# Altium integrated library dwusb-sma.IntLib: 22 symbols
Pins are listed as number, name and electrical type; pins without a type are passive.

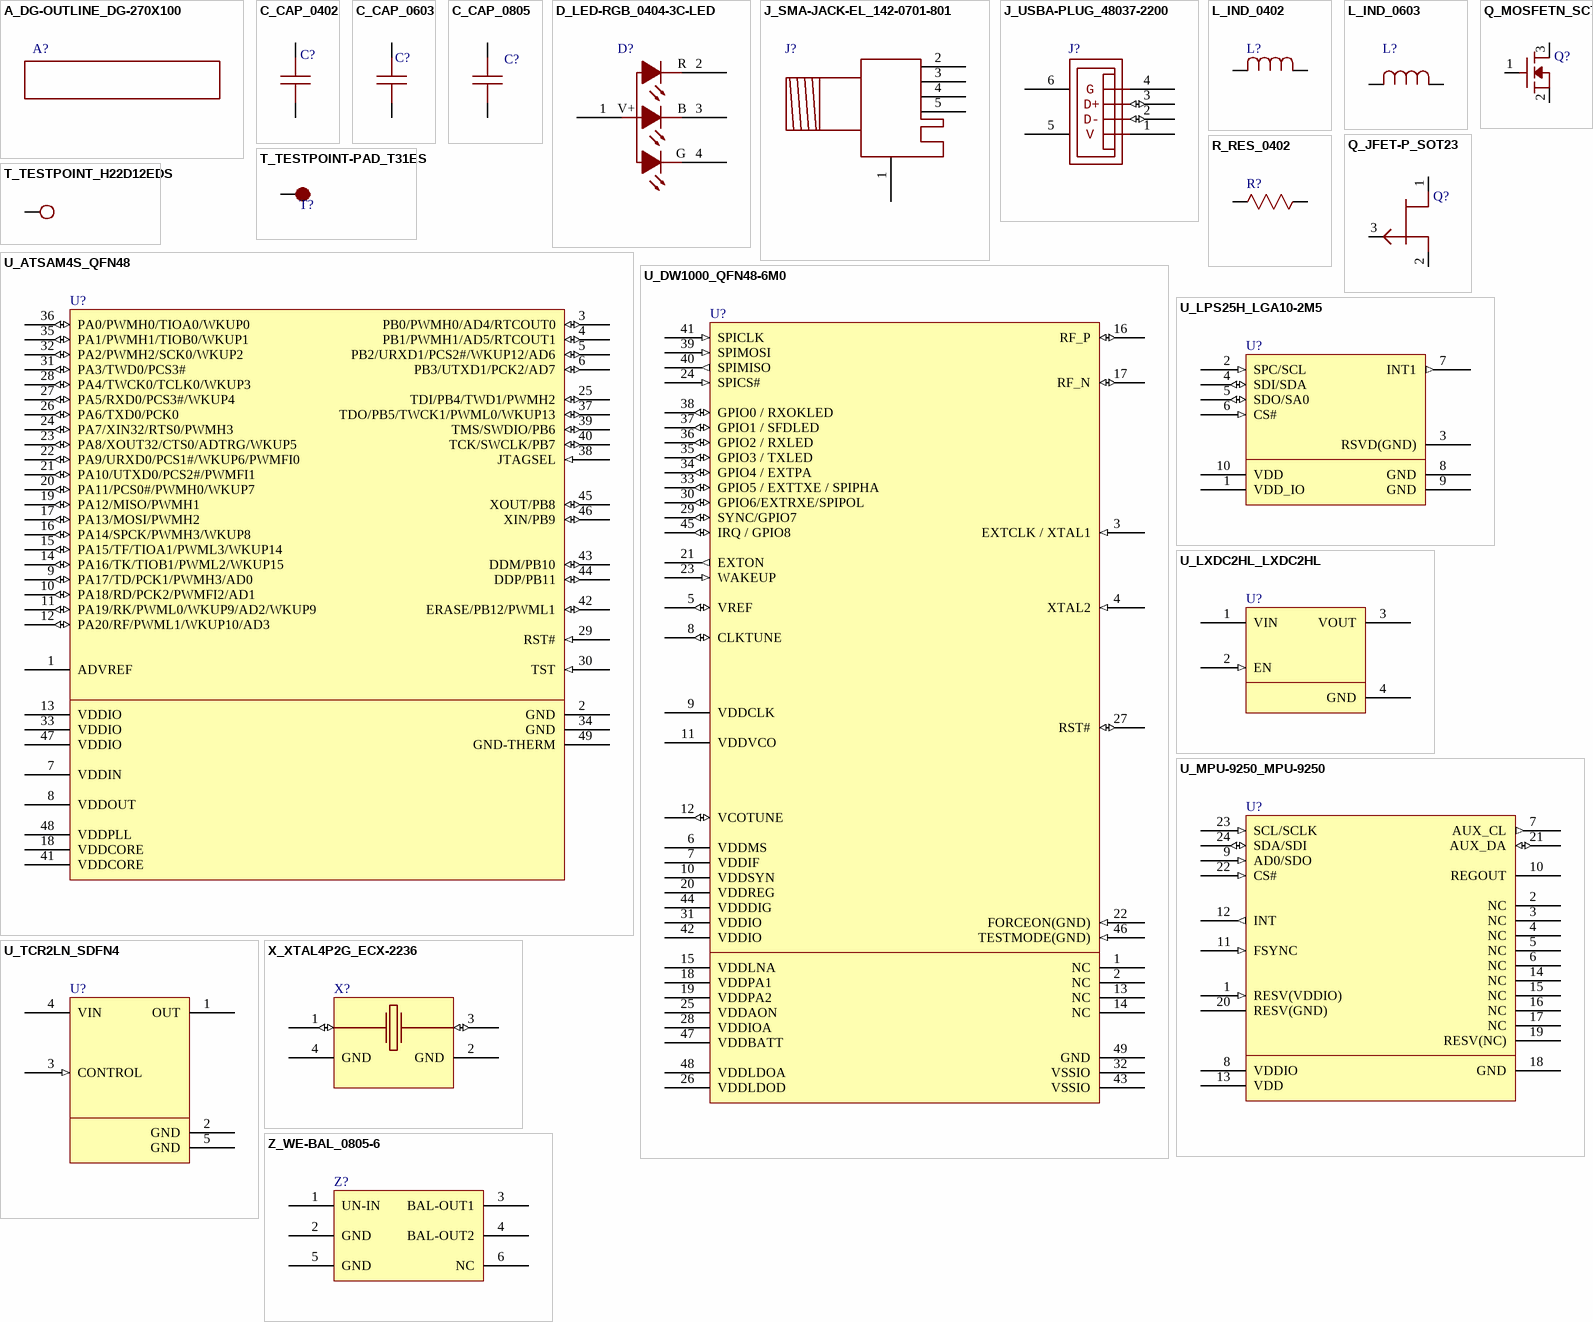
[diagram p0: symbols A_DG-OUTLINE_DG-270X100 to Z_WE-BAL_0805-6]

## A_DG-OUTLINE_DG-270X100
designator A?, comment A_DG-OUTLINE-DG-270X100  (value not drawn)
footprint DG-270X100

## C_CAP_0402
designator C?  (value not drawn)
footprint 0402
pins: 1, 2

## C_CAP_0603
designator C?  (value not drawn)
footprint 0603
pins: 1, 2

## C_CAP_0805
designator C?  (value not drawn)
footprint 0805
footprint 0805-S26
pins: 1, 2

## D_LED-RGB_0404-3C-LED
designator D?, comment LED RGB SQUARE CLEAR SMD  (value not drawn)
footprint 0404-3C-LED
pins: 1 V+, 2 R, 3 B, 4 G

## J_SMA-JACK-EL_142-0701-801
designator J?, comment J01340  (value not drawn)
footprint 142-0701-801
pins: 1, 2, 3, 4, 5

## J_USBA-PLUG_48037-2200
designator J?  (value not drawn)
footprint 48037-2200
pins: 1 +5V (power), 2 -DATA (io), 3 +DATA (io), 4 GND (power), 5 SHIELD (power), 6 SHIELD (power)

## L_IND_0402
designator L?  (value not drawn)
footprint 0402
pins: 1, 2

## L_IND_0603
designator L?  (value not drawn)
footprint 0603
pins: 1, 2

## Q_JFET-P_SOT23
designator Q?  (value not drawn)
footprint SOT23
pins: 1 D, 2 S, 3 G

## Q_MOSFETN_SC70
designator Q?, comment Q00171  (value not drawn)
footprint SC70
pins: 1 G, 2 S, 3 D

## R_RES_0402
designator R?  (value not drawn)
footprint 0402
pins: 1, 2

## T_TESTPOINT-PAD_T31ES
designator T?  (value not drawn)
footprint T31ES
pins: 1

## T_TESTPOINT_H22D12EDS
designator T?  (value not drawn)
footprint H22D12EDS
pins: 1

## U_ATSAM4S_QFN48
designator U?, comment U00965  (value not drawn)
footprint QFN48
pins: 1 ADVREF (power), 2 GND (power), 3 PB0/PWMH0/AD4/RTCOUT0 (io), 4 PB1/PWMH1/AD5/RTCOUT1 (io), 5 PB2/URXD1/PCS2#/WKUP12/AD6 (io), 6 PB3/UTXD1/PCK2/AD7 (io), 7 VDDIN (power), 8 VDDOUT (power), 9 PA17/TD/PCK1/PWMH3/AD0 (io), 10 PA18/RD/PCK2/PWMFI2/AD1 (io), 11 PA19/RK/PWML0/WKUP9/AD2/WKUP9 (io), 12 PA20/RF/PWML1/WKUP10/AD3 (io), 13 VDDIO (power), 14 PA16/TK/TIOB1/PWML2/WKUP15 (io), 15 PA15/TF/TIOA1/PWML3/WKUP14 (io), 16 PA14/SPCK/PWMH3/WKUP8 (io), 17 PA13/MOSI/PWMH2 (io), 18 VDDCORE (power), 19 PA12/MISO/PWMH1 (io), 20 PA11/PCS0#/PWMH0/WKUP7 (io), 21 PA10/UTXD0/PCS2#/PWMFI1 (io), 22 PA9/URXD0/PCS1#/WKUP6/PWMFI0 (io), 23 PA8/XOUT32/CTS0/ADTRG/WKUP5 (io), 24 PA7/XIN32/RTS0/PWMH3 (io), 25 TDI/PB4/TWD1/PWMH2 (io), 26 PA6/TXD0/PCK0 (io), 27 PA5/RXD0/PCS3#/WKUP4 (io), 28 PA4/TWCK0/TCLK0/WKUP3 (io), 29 RST# (in), 30 TST (in), 31 PA3/TWD0/PCS3# (io), 32 PA2/PWMH2/SCK0/WKUP2 (io), 33 VDDIO (power), 34 GND (power), 35 PA1/PWMH1/TIOB0/WKUP1 (io), 36 PA0/PWMH0/TIOA0/WKUP0 (io), 37 TDO/PB5/TWCK1/PWML0/WKUP13 (io), 38 JTAGSEL (in), 39 TMS/SWDIO/PB6 (io), 40 TCK/SWCLK/PB7 (io), 41 VDDCORE (power), 42 ERASE/PB12/PWML1 (io), 43 DDM/PB10 (io), 44 DDP/PB11 (io), 45 XOUT/PB8 (io), 46 XIN/PB9 (io), 47 VDDIO (power), 48 VDDPLL (power), 49 GND-THERM

## U_DW1000_QFN48-6M0
designator U?, comment U00956  (value not drawn)
footprint QFN48-6M0
pins: 1 NC, 2 NC, 3 EXTCLK / XTAL1 (in), 4 XTAL2 (in), 5 VREF (io), 6 VDDMS (power), 7 VDDIF (power), 8 CLKTUNE (io), 9 VDDCLK (power), 10 VDDSYN (power), 11 VDDVCO (power), 12 VCOTUNE (io), 13 NC, 14 NC, 15 VDDLNA (power), 16 RF_P (io), 17 RF_N (io), 18 VDDPA1 (power), 19 VDDPA2 (power), 20 VDDREG (power), 21 EXTON (out), 22 FORCEON(GND) (in), 23 WAKEUP (in), 24 SPICS# (in), 25 VDDAON (power), 26 VDDLDOD (power), 27 RST# (io), 28 VDDIOA (power), 29 SYNC/GPIO7 (io), 30 GPIO6/EXTRXE/SPIPOL (io), 31 VDDIO (power), 32 VSSIO (power), 33 GPIO5 / EXTTXE / SPIPHA (io), 34 GPIO4 / EXTPA (io), 35 GPIO3 / TXLED (io), 36 GPIO2 / RXLED (io), 37 GPIO1 / SFDLED (io), 38 GPIO0 / RXOKLED (io), 39 SPIMOSI (in), 40 SPIMISO (out), 41 SPICLK (in), 42 VDDIO (power), 43 VSSIO (power), 44 VDDDIG (power), 45 IRQ / GPIO8 (io), 46 TESTMODE(GND) (in), 47 VDDBATT (power), 48 VDDLDOA (power), 49 GND (power)

## U_LPS25H_LGA10-2M5
designator U?, comment U01153  (value not drawn)
footprint LGA10-2M5
pins: 1 VDD_IO (power), 2 SPC/SCL (in), 3 RSVD(GND), 4 SDI/SDA (io), 5 SDO/SA0 (io), 6 CS# (in), 7 INT1 (out), 8 GND (power), 9 GND (power), 10 VDD (power)

## U_LXDC2HL_LXDC2HL
designator U?  (value not drawn)
footprint LXDC2HL
pins: 1 VIN (power), 2 EN (in), 3 VOUT (power), 4 GND (power)

## U_MPU-9250_MPU-9250
designator U?, comment U00945  (value not drawn)
footprint MPU-9250
pins: 1 RESV(VDDIO) (in), 2 NC, 3 NC, 4 NC, 5 NC, 6 NC, 7 AUX_CL (out), 8 VDDIO (power), 9 AD0/SDO (in), 10 REGOUT (power), 11 FSYNC (in), 12 INT (out), 13 VDD (power), 14 NC, 15 NC, 16 NC, 17 NC, 18 GND (power), 19 RESV(NC), 20 RESV(GND) (power), 21 AUX_DA (io), 22 CS# (in), 23 SCL/SCLK (in), 24 SDA/SDI (io)

## U_TCR2LN_SDFN4
designator U?  (value not drawn)
footprint SDFN4
pins: 1 OUT (power), 2 GND (power), 3 CONTROL (in), 4 VIN (power), 5 GND (power)

## X_XTAL4P2G_ECX-2236
designator X?  (value not drawn)
footprint ECX-2236
pins: 1 X1 (io), 2 GND (power), 3 X2 (io), 4 GND (power)

## Z_WE-BAL_0805-6
designator Z?  (value not drawn)
footprint 0805-6
pins: 1 UN-IN, 2 GND, 3 BAL-OUT1, 4 BAL-OUT2, 5 GND, 6 NC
